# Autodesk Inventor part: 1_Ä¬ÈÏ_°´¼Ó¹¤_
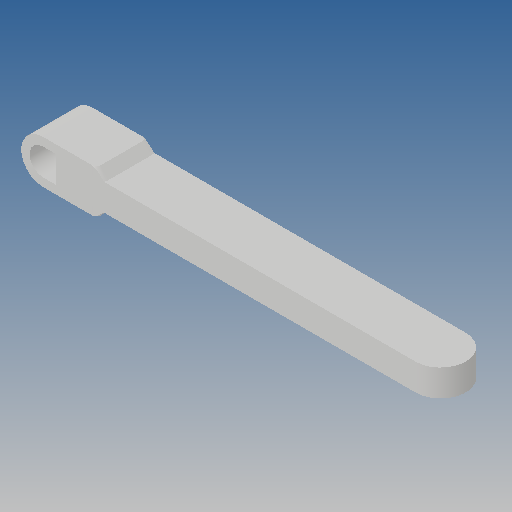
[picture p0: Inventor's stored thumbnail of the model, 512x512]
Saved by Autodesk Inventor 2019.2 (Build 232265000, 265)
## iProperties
Created: 2010-06
Part Number: 1_Ä¬ÈÏ_°´¼Ó¹¤_
Material: Ogólny
Document SubType Name: Modeling
Designer: CADENGINEERING4
Density: 1 g/cm^3
Appearance: Domyślna
Author: CADENGINEERING4
Revision Number: ÈÎºÎ
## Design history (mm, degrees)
feature "NONE"
feature "NONE:1"
feature "NONE:2"
feature "NONE:3"
node "Bryła1"
node "Bryła2"
node "Bryła3"
node "Bryła4"
